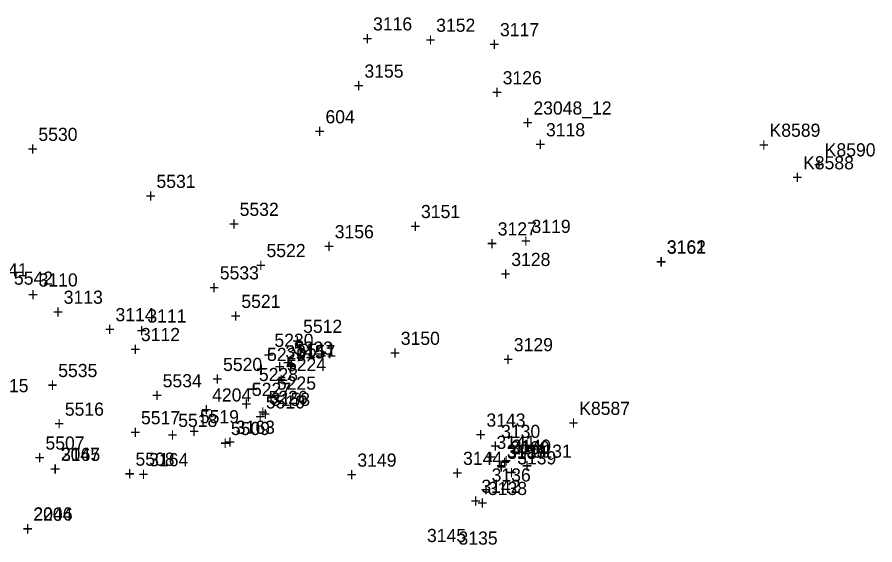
# Model space of a CAD drawing. Extents: x 1036751 to 1042192, y 772604 to 785439.
# Drawn here: x 1041276.4 to 1041439.5, y 774872.7 to 774973.1 of the extents above; entities that cross this region are included whole.
import ezdxf

# ---------------------------------------------------------------- set-up
doc = ezdxf.new("R2010")
doc.units = 0
for name, color, linetype in [('S_Control_Geodetic_ControlPoint', 7, 'Continuous'), ('S_Control_Temp_Traverse', 7, 'Continuous'), ('S_Curb_Type_3', 7, 'Continuous'), ('S_Drainage_Culvert_Top', 7, 'Continuous'), ('S_Drainage_DropInlet', 7, 'Continuous'), ('S_Drainage_Invert', 7, 'Continuous'), ('S_Ground_LevelString', 7, 'Continuous'), ('S_Misc_MiscItems', 7, 'Continuous'), ('S_Property_IronPipeFound', 7, 'Continuous'), ('S_Roadway_Centerline', 7, 'Continuous'), ('S_Roadway_Edge_Pavement', 7, 'Continuous'), ('S_Roadway_Edge_TW', 7, 'Continuous'), ('S_Traffic_Sign_SinglePost', 7, 'Continuous'), ('S_Utilities_Gas_Pump', 7, 'Continuous'), ('S_Utilities_Gas_PumpIsland', 7, 'Continuous'), ('S_Utilities_GuyWire3', 7, 'Continuous'), ('S_Utilities_Hydrant', 7, 'Continuous'), ('S_Utilities_Pole_Power', 7, 'Continuous'), ('S_Utilities_UG_Water_Gate', 7, 'Continuous')]:
    doc.layers.add(name, color=color, linetype=linetype)

msp = doc.modelspace()

# ---------------------------------------------------------------- texts
at = {"layer": 'S_Control_Geodetic_ControlPoint'}
for s, p in [('23048_12', (1041374.54, 774954.57)), ('+', (1041372.48, 774951.82))]:
    msp.add_text(s, height=2.5, dxfattribs=at).set_placement(p)
at = {"layer": 'S_Control_Temp_Traverse'}
for s, p in [('604', (1041335, 774952.9)), ('604', (1041335, 774952.9)), ('604', (1041335, 774952.9)), ('604', (1041335, 774952.9)), ('604', (1041335, 774952.9)), ('604', (1041335, 774952.9)), ('+', (1041332.94, 774950.15)), ('+', (1041332.94, 774950.15)), ('+', (1041332.94, 774950.15)), ('+', (1041332.94, 774950.15)), ('+', (1041332.94, 774950.15)), ('+', (1041332.94, 774950.15))]:
    msp.add_text(s, height=2.5, dxfattribs=at).set_placement(p)
at = {"layer": 'S_Curb_Type_3'}
for s, p in [('5230', (1041325.29, 774910.4)), ('5223', (1041328.98, 774908.91)), ('+', (1041323.23, 774907.65)), ('5229', (1041323.89, 774907.71)), ('+', (1041326.92, 774906.16)), ('5224', (1041327.67, 774905.78)), ('+', (1041321.83, 774904.96)), ('5228', (1041322.34, 774903.89)), ('+', (1041325.6, 774903.03)), ('5225', (1041325.76, 774902.25)), ('+', (1041320.28, 774901.14)), ('5227', (1041321.02, 774901.06)), ('+', (1041323.69, 774899.5)), ('5226', (1041324.18, 774899.53)), ('+', (1041318.96, 774898.31)), ('+', (1041322.11, 774896.78))]:
    msp.add_text(s, height=2.5, dxfattribs=at).set_placement(p)
at = {"layer": 'S_Drainage_Culvert_Top'}
for s, p in [('3161', (1041399.94, 774928.1)), ('+', (1041397.88, 774925.35)), ('3160', (1041370.16, 774889.96)), ('+', (1041368.1, 774887.21))]:
    msp.add_text(s, height=2.5, dxfattribs=at).set_placement(p)
at = {"layer": 'S_Drainage_DropInlet'}
for s, p in [('3116', (1041344.05, 774970.56)), ('3117', (1041368.19, 774969.47)), ('+', (1041341.99, 774967.81)), ('+', (1041366.13, 774966.72))]:
    msp.add_text(s, height=2.5, dxfattribs=at).set_placement(p)
at = {"layer": 'S_Drainage_Invert'}
for s, p in [('3162', (1041399.91, 774928.16)), ('+', (1041397.84, 774925.41)), ('3159', (1041369.49, 774889.32)), ('+', (1041367.43, 774886.57))]:
    msp.add_text(s, height=2.5, dxfattribs=at).set_placement(p)
at = {"layer": 'S_Ground_LevelString'}
for s, p in [('5530', (1041280.41, 774949.56)), ('+', (1041278.35, 774946.81)), ('5531', (1041302.86, 774940.62)), ('+', (1041300.8, 774937.87)), ('5532', (1041318.68, 774935.3)), ('+', (1041316.62, 774932.55)), ('5522', (1041323.79, 774927.46)), ('5541', (1041270.92, 774923.8)), ('5533', (1041314.91, 774923.22)), ('+', (1041321.73, 774924.71)), ('5542', (1041275.76, 774922.21)), ('+', (1041312.85, 774920.47)), ('5521', (1041319.01, 774917.8)), ('+', (1041316.95, 774915.05)), ('5512', (1041330.75, 774913.05)), ('+', (1041328.69, 774910.3)), ('5511', (1041329.6, 774908.52)), ('5520', (1041315.53, 774905.8)), ('+', (1041327.54, 774905.77)), ('5535', (1041284.18, 774904.65)), ('5534', (1041304.04, 774902.7)), ('+', (1041313.47, 774903.05)), ('5515', (1041271.09, 774901.77)), ('+', (1041282.12, 774901.9)), ('+', (1041301.98, 774899.95)), ('5510', (1041323.67, 774898.67)), ('5516', (1041285.44, 774897.3)), ('5517', (1041299.92, 774895.67)), ('5519', (1041311.11, 774895.86)), ('+', (1041321.61, 774895.92)), ('+', (1041283.38, 774894.55)), ('5518', (1041307, 774895.17)), ('3143', (1041365.61, 774895.22)), ('+', (1041297.86, 774892.92)), ('+', (1041309.05, 774893.11)), ('5509', (1041317.01, 774893.62)), ('+', (1041363.55, 774892.47)), ('5507', (1041281.75, 774890.86)), ('+', (1041304.94, 774892.42)), ('+', (1041314.95, 774890.87)), ('3141', (1041367.52, 774890.99)), ('3137', (1041369.55, 774889.08)), ('3140', (1041370.45, 774890.26)), ('+', (1041279.69, 774888.11)), ('5508', (1041298.87, 774887.79)), ('3144', (1041361.17, 774887.95)), ('+', (1041365.46, 774888.24)), ('3139', (1041371.46, 774888.04)), ('+', (1041367.49, 774886.33)), ('+', (1041368.39, 774887.51)), ('+', (1041296.81, 774885.04)), ('+', (1041359.11, 774885.2)), ('3136', (1041366.6, 774884.78)), ('+', (1041369.4, 774885.29)), ('3142', (1041364.65, 774882.63)), ('+', (1041364.53, 774882.03)), ('3138', (1041365.9, 774882.22)), ('+', (1041362.59, 774879.88)), ('+', (1041363.84, 774879.47)), ('2204', (1041279.43, 774877.32)), ('+', (1041277.37, 774874.57)), ('3145', (1041354.31, 774873.27)), ('3135', (1041360.3, 774872.78))]:
    msp.add_text(s, height=2.5, dxfattribs=at).set_placement(p)
at = {"layer": 'S_Misc_MiscItems'}
for s, p in [('4204', (1041313.45, 774900)), ('+', (1041311.39, 774897.25))]:
    msp.add_text(s, height=2.5, dxfattribs=at).set_placement(p)
at = {"layer": 'S_Property_IronPipeFound'}
for s, p in [('K8587', (1041383.25, 774897.45)), ('+', (1041381.19, 774894.7))]:
    msp.add_text(s, height=2.5, dxfattribs=at).set_placement(p)
at = {"layer": 'S_Roadway_Centerline'}
for s, p in [('3152', (1041356.06, 774970.31)), ('+', (1041354, 774967.56)), ('3151', (1041353.17, 774934.88)), ('+', (1041351.11, 774932.13)), ('3150', (1041349.32, 774910.77)), ('+', (1041347.26, 774908.02)), ('3149', (1041341.07, 774887.61)), ('+', (1041339.01, 774884.86))]:
    msp.add_text(s, height=2.5, dxfattribs=at).set_placement(p)
at = {"layer": 'S_Roadway_Edge_Pavement'}
for s, p in [('3155', (1041342.41, 774961.59)), ('3126', (1041368.7, 774960.32)), ('+', (1041340.35, 774958.84)), ('+', (1041366.64, 774957.57)), ('3127', (1041367.76, 774931.58)), ('3156', (1041336.76, 774931.04)), ('+', (1041365.7, 774928.84)), ('+', (1041334.7, 774928.29)), ('3128', (1041370.34, 774925.77)), ('+', (1041368.27, 774923.02)), ('3129', (1041370.82, 774909.56)), ('3157', (1041329.43, 774908.24)), ('+', (1041368.76, 774906.81)), ('+', (1041327.37, 774905.49)), ('3158', (1041324.63, 774899.16)), ('+', (1041322.57, 774896.41)), ('3163', (1041317.95, 774893.86)), ('3130', (1041368.4, 774893.07)), ('+', (1041315.89, 774891.11)), ('+', (1041366.34, 774890.32)), ('3131', (1041374.4, 774889.31)), ('2047', (1041284.67, 774888.72)), ('3165', (1041284.73, 774888.7)), ('3164', (1041301.48, 774887.69)), ('+', (1041282.61, 774885.97)), ('+', (1041282.67, 774885.95)), ('+', (1041372.34, 774886.56)), ('+', (1041299.42, 774884.94))]:
    msp.add_text(s, height=2.5, dxfattribs=at).set_placement(p)
at = {"layer": 'S_Roadway_Edge_TW'}
for s, p in [('2046', (1041279.47, 774877.38)), ('+', (1041277.41, 774874.63))]:
    msp.add_text(s, height=2.5, dxfattribs=at).set_placement(p)
at = {"layer": 'S_Traffic_Sign_SinglePost'}
for s, p in [('3115', (1041327.39, 774908.19)), ('+', (1041325.33, 774905.44))]:
    msp.add_text(s, height=2.5, dxfattribs=at).set_placement(p)
at = {"layer": 'S_Utilities_Gas_Pump'}
for s, p in [('3113', (1041285.23, 774918.59)), ('+', (1041283.17, 774915.84)), ('3114', (1041295.07, 774915.27)), ('+', (1041293.01, 774912.52))]:
    msp.add_text(s, height=2.5, dxfattribs=at).set_placement(p)
at = {"layer": 'S_Utilities_Gas_PumpIsland'}
for s, p in [('3110', (1041280.45, 774921.87)), ('+', (1041278.39, 774919.12)), ('3111', (1041301.13, 774915.01)), ('+', (1041299.07, 774912.26)), ('3112', (1041299.91, 774911.49)), ('+', (1041297.85, 774908.74))]:
    msp.add_text(s, height=2.5, dxfattribs=at).set_placement(p)
at = {"layer": 'S_Utilities_GuyWire3'}
for s, p in [('3119', (1041374.19, 774932.06)), ('+', (1041372.13, 774929.31))]:
    msp.add_text(s, height=2.5, dxfattribs=at).set_placement(p)
at = {"layer": 'S_Utilities_Hydrant'}
for s, p in [('K8589', (1041419.45, 774950.34)), ('+', (1041417.39, 774947.59))]:
    msp.add_text(s, height=2.5, dxfattribs=at).set_placement(p)
at = {"layer": 'S_Utilities_Pole_Power'}
for s, p in [('3118', (1041376.94, 774950.43)), ('+', (1041374.88, 774947.68))]:
    msp.add_text(s, height=2.5, dxfattribs=at).set_placement(p)
at = {"layer": 'S_Utilities_UG_Water_Gate'}
for s, p in [('K8590', (1041429.94, 774946.61)), ('K8588', (1041425.83, 774944.15)), ('+', (1041427.88, 774943.86)), ('+', (1041423.77, 774941.4))]:
    msp.add_text(s, height=2.5, dxfattribs=at).set_placement(p)

doc.saveas('drawing.dxf')
